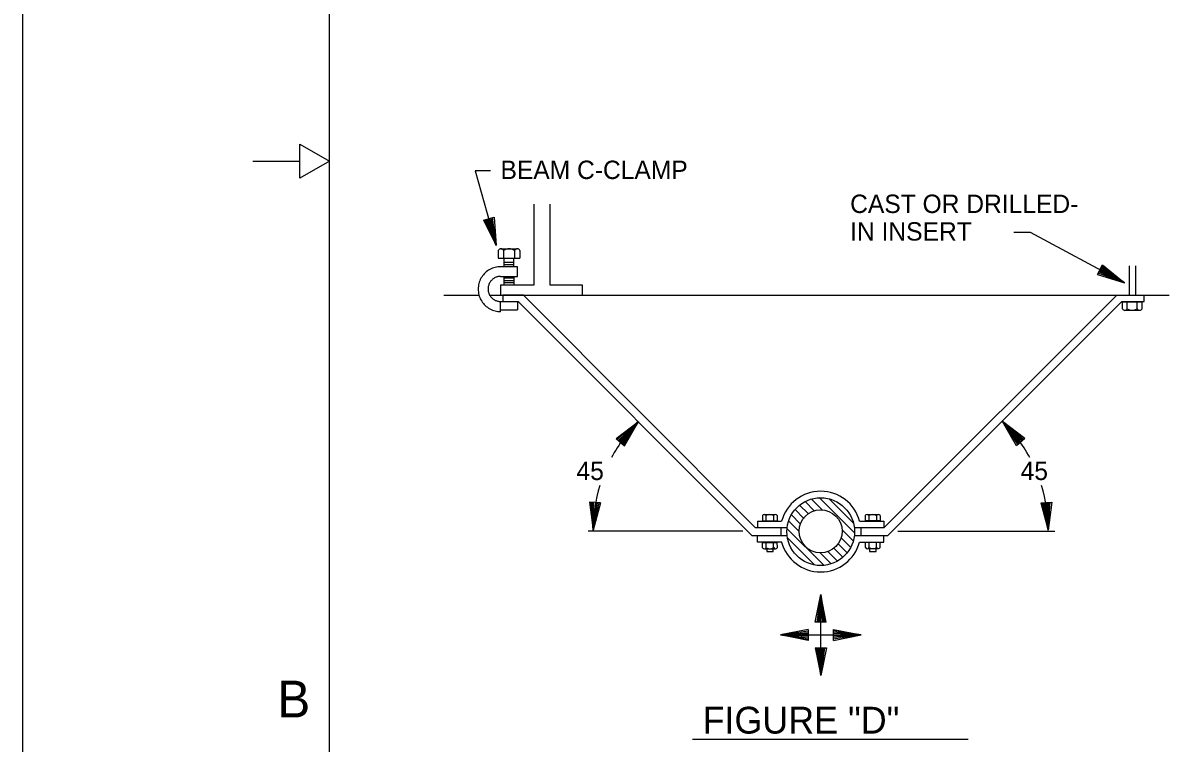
# Model space of a CAD drawing. Extents: x 9999.96 to 10005.26, y 9999.88 to 10002.38.
# Drawn here: x 9999.96 to 10000.584, y 10000.818 to 10001.21 of the extents above; entities that cross this region are included whole.
import ezdxf

# ---------------------------------------------------------------- set-up
doc = ezdxf.new("R2010")
doc.units = 0
doc.layers.add('Level 1', color=7, linetype='Continuous')
doc.layers.add('Level 2', color=7, linetype='Continuous')

msp = doc.modelspace()

# ---------------------------------------------------------------- linework, layer by layer
at = {"layer": 'Level 1'}
for p, q in [((9999.96033, 9999.88453), (9999.96033, 10002.38453)), ((10000.127, 9999.9262), (10000.127, 10002.34286)), ((10000.111, 10001.1252), (10000.111, 10001.14361)), ((10000.111, 10001.14361), (10000.127, 10001.13453)), ((10000.08533, 10001.13453), (10000.111, 10001.13453)), ((10000.127, 10001.13453), (10000.111, 10001.1252))]:
    msp.add_line(p, q, dxfattribs=at)
at = {"layer": 'Level 2'}
for p, q in [((10000.23844, 10001.06725), (10000.23844, 10001.11107)), ((10000.24683, 10001.11107), (10000.24683, 10001.06725)), ((10000.21073, 10001.10229), (10000.21652, 10001.10394)), ((10000.21073, 10001.10229), (10000.21773, 10001.08864)), ((10000.21773, 10001.08864), (10000.21146, 10001.10251)), ((10000.21773, 10001.08864), (10000.21227, 10001.10276)), ((10000.21773, 10001.08864), (10000.21292, 10001.10292)), ((10000.21359, 10001.10313), (10000.21773, 10001.08864)), ((10000.21773, 10001.08864), (10000.21432, 10001.10331)), ((10000.21773, 10001.08864), (10000.21503, 10001.10353)), ((10000.21773, 10001.08864), (10000.21573, 10001.10372)), ((10000.21652, 10001.10394), (10000.21773, 10001.08864)), ((10000.21886, 10001.0859), (10000.21883, 10001.08178)), ((10000.21883, 10001.08178), (10000.23064, 10001.08178)), ((10000.22031, 10001.08678), (10000.22915, 10001.08678)), ((10000.22176, 10001.08589), (10000.22176, 10001.08178)), ((10000.22211, 10001.07704), (10000.22211, 10001.08174)), ((10000.22725, 10001.07704), (10000.22725, 10001.08174)), ((10000.2277, 10001.0859), (10000.2277, 10001.08175)), ((10000.23063, 10001.0859), (10000.23064, 10001.08178)), ((10000.22929, 10001.07704), (10000.22014, 10001.07704)), ((10000.22728, 10001.07931), (10000.22209, 10001.07931)), ((10000.22209, 10001.07826), (10000.22728, 10001.07826)), ((10000.22929, 10001.07178), (10000.22929, 10001.07704)), ((10000.54464, 10001.0728), (10000.54748, 10001.07811)), ((10000.54603, 10001.07544), (10000.55932, 10001.06835)), ((10000.55932, 10001.06835), (10000.5464, 10001.0761)), ((10000.55932, 10001.06835), (10000.54674, 10001.07676)), ((10000.55932, 10001.06835), (10000.54708, 10001.0774)), ((10000.54748, 10001.07811), (10000.55932, 10001.06835)), ((10000.56197, 10001.07755), (10000.56197, 10001.06167)), ((10000.56538, 10001.07755), (10000.56538, 10001.06167)), ((10000.22014, 10001.07178), (10000.22929, 10001.07178)), ((10000.22728, 10001.0709), (10000.22209, 10001.0709)), ((10000.22211, 10001.06721), (10000.22211, 10001.07182)), ((10000.22216, 10001.06948), (10000.22728, 10001.06948)), ((10000.22725, 10001.07182), (10000.22725, 10001.06721)), ((10000.54464, 10001.0728), (10000.55932, 10001.06835)), ((10000.55932, 10001.06835), (10000.54499, 10001.07348)), ((10000.55932, 10001.06835), (10000.54538, 10001.07424)), ((10000.55932, 10001.06835), (10000.54571, 10001.07481)), ((10000.22014, 10001.06725), (10000.23844, 10001.06725)), ((10000.22014, 10001.06725), (10000.22014, 10001.06154)), ((10000.22722, 10001.06835), (10000.22209, 10001.06835)), ((10000.24683, 10001.06725), (10000.26447, 10001.06725)), ((10000.26447, 10001.06725), (10000.26447, 10001.06154)), ((10000.18919, 10001.0616), (10000.20834, 10001.0616)), ((10000.21416, 10001.0616), (10000.58364, 10001.0616)), ((10000.22014, 10001.0582), (10000.22973, 10001.0582)), ((10000.22014, 10001.05258), (10000.22014, 10001.0581)), ((10000.23256, 10001.0616), (10000.22138, 10001.06154)), ((10000.22138, 10001.06154), (10000.22138, 10001.0582)), ((10000.22932, 10001.0581), (10000.22932, 10001.0536)), ((10000.22973, 10001.0582), (10000.35664, 10000.93081)), ((10000.23256, 10001.0616), (10000.35853, 10000.93516)), ((10000.42875, 10000.93521), (10000.55515, 10001.0616)), ((10000.4306, 10000.93081), (10000.55797, 10001.05818)), ((10000.55519, 10001.0616), (10000.57004, 10001.0616)), ((10000.55797, 10001.05818), (10000.57004, 10001.05818)), ((10000.55823, 10001.05789), (10000.56895, 10001.05789)), ((10000.55825, 10001.05413), (10000.55823, 10001.05789)), ((10000.56089, 10001.05416), (10000.56089, 10001.05786)), ((10000.56629, 10001.05416), (10000.56629, 10001.0579)), ((10000.56897, 10001.05417), (10000.56895, 10001.05789)), ((10000.57004, 10001.05818), (10000.57004, 10001.0616)), ((10000.22014, 10001.0536), (10000.22932, 10001.0536)), ((10000.55958, 10001.05332), (10000.56761, 10001.0534)), ((10000.28297, 10000.98359), (10000.29516, 10000.99294)), ((10000.29516, 10000.99294), (10000.28354, 10000.98309)), ((10000.29516, 10000.99294), (10000.28417, 10000.98252)), ((10000.29516, 10000.99294), (10000.28468, 10000.9821)), ((10000.2852, 10000.98164), (10000.29516, 10000.99294)), ((10000.29516, 10000.99294), (10000.28578, 10000.98114)), ((10000.29516, 10000.99294), (10000.28632, 10000.98064)), ((10000.29516, 10000.99294), (10000.28688, 10000.98018)), ((10000.28751, 10000.97964), (10000.29516, 10000.99294)), ((10000.50305, 10000.98164), (10000.49309, 10000.99294)), ((10000.50074, 10000.97964), (10000.49309, 10000.99294)), ((10000.50528, 10000.98359), (10000.49309, 10000.99294)), ((10000.49309, 10000.99294), (10000.50193, 10000.98064)), ((10000.49309, 10000.99294), (10000.50408, 10000.98252)), ((10000.49309, 10000.99294), (10000.50138, 10000.98018)), ((10000.49309, 10000.99294), (10000.50247, 10000.98114)), ((10000.49309, 10000.99294), (10000.50357, 10000.9821)), ((10000.49309, 10000.99294), (10000.50471, 10000.98309)), ((10000.28297, 10000.98359), (10000.28751, 10000.97964)), ((10000.50528, 10000.98359), (10000.50074, 10000.97964)), ((10000.39499, 10000.94485), (10000.38914, 10000.95072)), ((10000.4127, 10000.93206), (10000.39331, 10000.95145)), ((10000.4122, 10000.93746), (10000.39869, 10000.95095)), ((10000.27443, 10000.94856), (10000.26841, 10000.94899)), ((10000.26841, 10000.94899), (10000.27038, 10000.93376)), ((10000.27038, 10000.93376), (10000.26923, 10000.94893)), ((10000.27038, 10000.93376), (10000.26995, 10000.9489)), ((10000.27038, 10000.93376), (10000.2707, 10000.94883)), ((10000.27145, 10000.94878), (10000.27038, 10000.93376)), ((10000.27038, 10000.93376), (10000.27216, 10000.94873)), ((10000.27038, 10000.93376), (10000.27282, 10000.9487)), ((10000.27038, 10000.93376), (10000.27366, 10000.94863)), ((10000.27443, 10000.94856), (10000.27038, 10000.93376)), ((10000.38485, 10000.94034), (10000.38025, 10000.94495)), ((10000.38734, 10000.94275), (10000.38272, 10000.94736)), ((10000.3906, 10000.94435), (10000.38567, 10000.9493)), ((10000.51382, 10000.94856), (10000.51984, 10000.94899)), ((10000.51382, 10000.94856), (10000.51788, 10000.93376)), ((10000.51788, 10000.93376), (10000.51459, 10000.94863)), ((10000.51788, 10000.93376), (10000.51543, 10000.9487)), ((10000.51788, 10000.93376), (10000.51609, 10000.94873)), ((10000.5168, 10000.94878), (10000.51788, 10000.93376)), ((10000.51788, 10000.93376), (10000.51755, 10000.94883)), ((10000.51984, 10000.94899), (10000.51788, 10000.93376)), ((10000.51788, 10000.93376), (10000.51902, 10000.94893)), ((10000.51788, 10000.93376), (10000.5183, 10000.9489)), ((10000.35978, 10000.93867), (10000.35978, 10000.93516)), ((10000.35986, 10000.93865), (10000.37295, 10000.93865)), ((10000.36245, 10000.94169), (10000.36244, 10000.93888)), ((10000.36244, 10000.93888), (10000.37049, 10000.93888)), ((10000.36345, 10000.94229), (10000.36948, 10000.94229)), ((10000.36443, 10000.94168), (10000.36443, 10000.93888)), ((10000.36848, 10000.94169), (10000.36848, 10000.93886)), ((10000.37048, 10000.94169), (10000.37049, 10000.93888)), ((10000.38242, 10000.933), (10000.37678, 10000.93865)), ((10000.3831, 10000.9372), (10000.37825, 10000.94205)), ((10000.41533, 10000.93867), (10000.4285, 10000.93867)), ((10000.41841, 10000.94175), (10000.4184, 10000.93894)), ((10000.4184, 10000.93894), (10000.42645, 10000.93894)), ((10000.41941, 10000.94235), (10000.42544, 10000.94235)), ((10000.42039, 10000.94175), (10000.42039, 10000.93894)), ((10000.42444, 10000.94175), (10000.42444, 10000.93894)), ((10000.42644, 10000.94175), (10000.42645, 10000.93894)), ((10000.4285, 10000.93867), (10000.4285, 10000.93524)), ((10000.35191, 10000.93316), (10000.26772, 10000.93316)), ((10000.35853, 10000.93516), (10000.37245, 10000.93516)), ((10000.37245, 10000.93516), (10000.37248, 10000.93081)), ((10000.37245, 10000.93516), (10000.37585, 10000.93516)), ((10000.39582, 10000.91472), (10000.37598, 10000.93456)), ((10000.41197, 10000.92786), (10000.40581, 10000.93404)), ((10000.41245, 10000.93521), (10000.41603, 10000.93521)), ((10000.41603, 10000.93521), (10000.41606, 10000.93081)), ((10000.41603, 10000.93521), (10000.42875, 10000.93521)), ((10000.43608, 10000.93316), (10000.52152, 10000.93316)), ((10000.35664, 10000.93081), (10000.37248, 10000.93081)), ((10000.35979, 10000.9273), (10000.35979, 10000.93081)), ((10000.37296, 10000.9273), (10000.35979, 10000.9273)), ((10000.36252, 10000.92701), (10000.37057, 10000.92711)), ((10000.36257, 10000.9242), (10000.36252, 10000.92701)), ((10000.36455, 10000.92423), (10000.36452, 10000.92702)), ((10000.3686, 10000.92428), (10000.36857, 10000.9271)), ((10000.37063, 10000.92431), (10000.37057, 10000.92711)), ((10000.37248, 10000.93081), (10000.37585, 10000.93081)), ((10000.39061, 10000.91502), (10000.37628, 10000.92934)), ((10000.40861, 10000.92146), (10000.40369, 10000.9264)), ((10000.41055, 10000.92442), (10000.4053, 10000.92967)), ((10000.41246, 10000.93081), (10000.41606, 10000.93081)), ((10000.41533, 10000.9273), (10000.4285, 10000.9273)), ((10000.41606, 10000.93081), (10000.4306, 10000.93081)), ((10000.41848, 10000.92707), (10000.42653, 10000.92719)), ((10000.41853, 10000.92426), (10000.41848, 10000.92707)), ((10000.42052, 10000.9243), (10000.42048, 10000.9271)), ((10000.42456, 10000.92434), (10000.42453, 10000.92717)), ((10000.42657, 10000.92439), (10000.42653, 10000.92719)), ((10000.4285, 10000.9273), (10000.4285, 10000.93081)), ((10000.36358, 10000.92361), (10000.36961, 10000.9237)), ((10000.39991, 10000.91552), (10000.39396, 10000.92147)), ((10000.40331, 10000.91699), (10000.39814, 10000.92217)), ((10000.4062, 10000.919), (10000.40129, 10000.92391)), ((10000.41954, 10000.92368), (10000.42558, 10000.92376)), ((10000.39121, 10000.88375), (10000.39423, 10000.89879)), ((10000.39423, 10000.89879), (10000.39202, 10000.88374)), ((10000.39423, 10000.89879), (10000.39275, 10000.88373)), ((10000.39423, 10000.89879), (10000.39349, 10000.88374)), ((10000.39423, 10000.8548), (10000.39423, 10000.89879)), ((10000.39425, 10000.88373), (10000.39423, 10000.89879)), ((10000.39723, 10000.88374), (10000.39423, 10000.89879)), ((10000.39423, 10000.89879), (10000.39563, 10000.88372)), ((10000.39423, 10000.89879), (10000.39495, 10000.88374)), ((10000.39423, 10000.89879), (10000.39647, 10000.88374)), ((10000.39723, 10000.88374), (10000.39121, 10000.88375)), ((10000.38729, 10000.87979), (10000.37224, 10000.87679)), ((10000.37224, 10000.87679), (10000.38729, 10000.87903)), ((10000.37224, 10000.87679), (10000.38731, 10000.87819)), ((10000.37224, 10000.87679), (10000.38729, 10000.87751)), ((10000.3873, 10000.87681), (10000.37224, 10000.87679)), ((10000.37224, 10000.87679), (10000.41623, 10000.87679)), ((10000.38728, 10000.87377), (10000.37224, 10000.87679)), ((10000.37224, 10000.87679), (10000.3873, 10000.87531)), ((10000.37224, 10000.87679), (10000.38729, 10000.87458)), ((10000.37224, 10000.87679), (10000.38729, 10000.87605)), ((10000.38729, 10000.87979), (10000.38728, 10000.87377)), ((10000.41623, 10000.87679), (10000.40116, 10000.8754)), ((10000.41623, 10000.87679), (10000.40117, 10000.87827)), ((10000.40117, 10000.87677), (10000.41623, 10000.87679)), ((10000.40118, 10000.87379), (10000.40119, 10000.87981)), ((10000.41623, 10000.87679), (10000.40118, 10000.879)), ((10000.41623, 10000.87679), (10000.40118, 10000.87753)), ((10000.40118, 10000.87379), (10000.41623, 10000.87679)), ((10000.41623, 10000.87679), (10000.40118, 10000.87607)), ((10000.41623, 10000.87679), (10000.40118, 10000.87455)), ((10000.40119, 10000.87981), (10000.41623, 10000.87679)), ((10000.39123, 10000.86985), (10000.39725, 10000.86984)), ((10000.39123, 10000.86985), (10000.39423, 10000.8548)), ((10000.39423, 10000.8548), (10000.39199, 10000.86985)), ((10000.39423, 10000.8548), (10000.39283, 10000.86988)), ((10000.39423, 10000.8548), (10000.39351, 10000.86985)), ((10000.39421, 10000.86986), (10000.39423, 10000.8548)), ((10000.39423, 10000.8548), (10000.39571, 10000.86986)), ((10000.39423, 10000.8548), (10000.39644, 10000.86985)), ((10000.39423, 10000.8548), (10000.39497, 10000.86985)), ((10000.39725, 10000.86984), (10000.39423, 10000.8548)), ((10000.32438, 10000.82011), (10000.4743, 10000.82011))]:
    msp.add_line(p, q, dxfattribs=at)
for points in [[(10000.21454, 10001.1292), (10000.2062, 10001.1292), (10000.21773, 10001.08864)], [(10000.49928, 10001.09579), (10000.50802, 10001.09579), (10000.55932, 10001.06835)], [(10000.22014, 10001.07706), (10000.21936, 10001.07704), (10000.2186, 10001.07697), (10000.21784, 10001.07684), (10000.21709, 10001.07668), (10000.21635, 10001.07647), (10000.21564, 10001.07621), (10000.21493, 10001.0759), (10000.21425, 10001.07555), (10000.21358, 10001.07517), (10000.21295, 10001.07473), (10000.21234, 10001.07426), (10000.21177, 10001.07375), (10000.21123, 10001.07321), (10000.21072, 10001.07264), (10000.21025, 10001.07203), (10000.20981, 10001.0714), (10000.20943, 10001.07073), (10000.20908, 10001.07005), (10000.20877, 10001.06934), (10000.20851, 10001.06863), (10000.2083, 10001.06789), (10000.20814, 10001.06714), (10000.20801, 10001.06638), (10000.20794, 10001.06561), (10000.20792, 10001.06484), (10000.20794, 10001.06408), (10000.20801, 10001.06331), (10000.20814, 10001.06256), (10000.2083, 10001.06181), (10000.20851, 10001.06107), (10000.20877, 10001.06035), (10000.20908, 10001.05965), (10000.20943, 10001.05896), (10000.20981, 10001.0583), (10000.21025, 10001.05767), (10000.21072, 10001.05706), (10000.21123, 10001.05649), (10000.21177, 10001.05594), (10000.21234, 10001.05544), (10000.21295, 10001.05497), (10000.21358, 10001.05453), (10000.21425, 10001.05415), (10000.21493, 10001.05379), (10000.21564, 10001.05349), (10000.21635, 10001.05323), (10000.21709, 10001.05301), (10000.21784, 10001.05284), (10000.2186, 10001.05273), (10000.21936, 10001.05266), (10000.22014, 10001.05264)], [(10000.22014, 10001.07178), (10000.2197, 10001.07177), (10000.21927, 10001.07173), (10000.21885, 10001.07167), (10000.21843, 10001.07157), (10000.21802, 10001.07145), (10000.21761, 10001.0713), (10000.21722, 10001.07114), (10000.21683, 10001.07094), (10000.21647, 10001.07072), (10000.21611, 10001.07048), (10000.21577, 10001.07022), (10000.21545, 10001.06993), (10000.21515, 10001.06963), (10000.21486, 10001.0693), (10000.21459, 10001.06897), (10000.21435, 10001.06861), (10000.21414, 10001.06824), (10000.21394, 10001.06785), (10000.21377, 10001.06746), (10000.21363, 10001.06706), (10000.21351, 10001.06665), (10000.21342, 10001.06623), (10000.21334, 10001.0658), (10000.2133, 10001.06538), (10000.21329, 10001.06495), (10000.2133, 10001.06452), (10000.21334, 10001.06408), (10000.21342, 10001.06367), (10000.21351, 10001.06324), (10000.21363, 10001.06283), (10000.21377, 10001.06243), (10000.21394, 10001.06203), (10000.21414, 10001.06165), (10000.21435, 10001.06128), (10000.21459, 10001.06093), (10000.21486, 10001.06058), (10000.21515, 10001.06026), (10000.21545, 10001.05996), (10000.21577, 10001.05968), (10000.21611, 10001.05941), (10000.21647, 10001.05917), (10000.21683, 10001.05895), (10000.21722, 10001.05876), (10000.21761, 10001.05858), (10000.21802, 10001.05844), (10000.21843, 10001.05832), (10000.21885, 10001.05823), (10000.21927, 10001.05816), (10000.2197, 10001.05811), (10000.22014, 10001.0581)], [(10000.3648, 10000.92366), (10000.36481, 10000.92208), (10000.36836, 10000.92208), (10000.36836, 10000.92366)], [(10000.42075, 10000.92373), (10000.42076, 10000.92215), (10000.42431, 10000.92215), (10000.42431, 10000.92373)]]:
    msp.add_lwpolyline(points, dxfattribs=at)
for centre, radius in [((10000.39418, 10000.93296), 0.01841), ((10000.39412, 10000.93318), 0.01172)]:
    msp.add_circle(centre, radius, dxfattribs=at)
for centre, radius, start, end in [((10000.2203, 10001.08512), 0.00165, 27.91313, 152.05962), ((10000.22472, 10001.08132), 0.00545, 57.03159, 122.96841), ((10000.22916, 10001.0851), 0.00167, 28.34206, 151.66132), ((10000.55957, 10001.05484), 0.0015, 208.16061, 332.3071), ((10000.56357, 10001.05831), 0.00495, 237.25183, 303.18864), ((10000.56762, 10001.05489), 0.00152, 208.55891, 331.87817), ((10000.35343, 10000.93377), 0.08305, 134.56125, 151.61924), ((10000.43482, 10000.93377), 0.08305, 28.38076, 45.43875), ((10000.35343, 10000.93377), 0.08305, 162.97004, 180), ((10000.43482, 10000.93377), 0.08305, 0, 17.02996), ((10000.39414, 10000.93298), 0.02194, 15.01092, 164.9726), ((10000.36344, 10000.94116), 0.00113, 27.91313, 152.05962), ((10000.36646, 10000.93856), 0.00372, 57.03159, 122.96841), ((10000.36949, 10000.94114), 0.00114, 28.34206, 151.66132), ((10000.41939, 10000.94122), 0.00113, 27.91313, 152.05962), ((10000.42241, 10000.93863), 0.00372, 57.03159, 122.96841), ((10000.42544, 10000.94121), 0.00114, 28.34206, 151.66132), ((10000.39414, 10000.93298), 0.02194, 194.97776, 344.98899), ((10000.36356, 10000.92474), 0.00113, 208.78561, 332.9321), ((10000.36654, 10000.92738), 0.00372, 237.87682, 303.81364), ((10000.36961, 10000.92484), 0.00114, 209.18391, 332.50317), ((10000.41951, 10000.9248), 0.00113, 208.78561, 332.9321), ((10000.4225, 10000.92744), 0.00372, 237.87682, 303.81364), ((10000.42556, 10000.92491), 0.00114, 209.18391, 332.50317)]:
    msp.add_arc(centre, radius, start, end, dxfattribs=at)

# ---------------------------------------------------------------- texts
at = {"layer": 'Level 1'}
msp.add_text('B', height=0.02, dxfattribs=at).set_placement((10000.09875, 10000.83191))
at = {"layer": 'Level 2'}
for s, height, p in [('BEAM C-CLAMP', 0.01, (10000.22006, 10001.12473)), ('CAST OR DRILLED-', 0.01, (10000.4102, 10001.10625)), ('IN INSERT', 0.01, (10000.4102, 10001.09125)), ('45', 0.01, (10000.26138, 10000.96104)), ('45', 0.01, (10000.5029, 10000.96104)), ('FIGURE "D"', 0.014583, (10000.32995, 10000.82315))]:
    msp.add_text(s, height=height, dxfattribs=at).set_placement(p)

doc.saveas('drawing.dxf')
